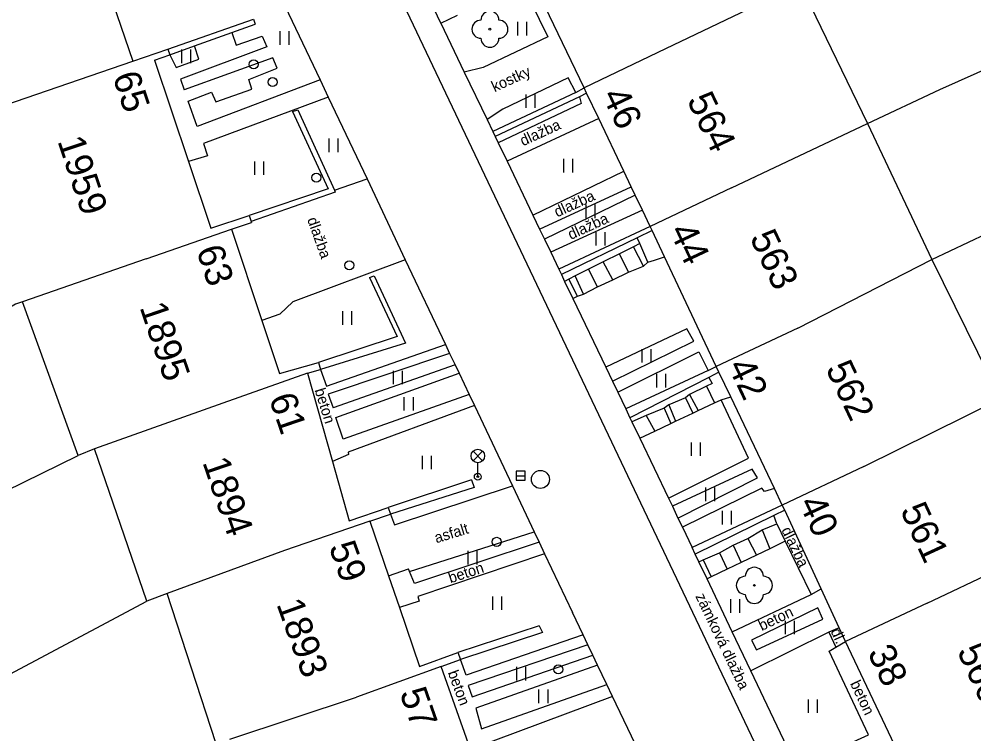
# Model space of a CAD drawing. Extents: x -493753 to -49290, y -1127285 to -112654.
# Drawn here: x -493226.3 to -493173.4, y -1127082.4 to -1127042.8 of the extents above; entities that cross this region are included whole.
import ezdxf

# ---------------------------------------------------------------- set-up
doc = ezdxf.new("R2010")
doc.units = 0
for name, color, linetype in [('Vrstva 10', 7, 'Continuous'), ('Vrstva 11', 7, 'Continuous'), ('Vrstva 22', 7, 'Continuous'), ('Vrstva 27', 7, 'Continuous'), ('Vrstva 28', 7, 'Continuous'), ('Vrstva 33', 7, 'Continuous'), ('Vrstva 36', 7, 'Continuous'), ('Vrstva 40', 7, 'Continuous'), ('Vrstva 43', 7, 'Continuous'), ('Vrstva 44', 7, 'Continuous'), ('Vrstva 5', 7, 'Continuous'), ('Vrstva 7', 7, 'Continuous')]:
    doc.layers.add(name, color=color, linetype=linetype)

msp = doc.modelspace()

# ---------------------------------------------------------------- linework, layer by layer
at = {"layer": 'Vrstva 10'}
for p, q in [((-493205.89, -1127040.18), (-493179.72, -1127095.23)), ((-493188.12, -1127062.66), (-493187.94, -1127063)), ((-493187.94, -1127063), (-493188.26, -1127063.14)), ((-493197.52, -1127071.79), (-493204.43, -1127074.07)), ((-493205.86, -1127073.65), (-493204.76, -1127073.27)), ((-493182.08, -1127075.43), (-493185.76, -1127077.21)), ((-493181.81, -1127076.05), (-493182.08, -1127075.43)), ((-493185.49, -1127077.76), (-493181.81, -1127076.05)), ((-493185.76, -1127077.21), (-493185.49, -1127077.76))]:
    msp.add_line(p, q, dxfattribs=at)
for points in [[(-493260.05, -1127044.84), (-493224.71, -1127032.96), (-493223.22, -1127032.61), (-493221.74, -1127032.78), (-493219.88, -1127033.49), (-493218.04, -1127034.37), (-493216.09, -1127035.82), (-493214.61, -1127037.23), (-493213.32, -1127038.83), (-493211.79, -1127041.66), (-493209.65, -1127046.18), (-493209.2, -1127047.13), (-493207.05, -1127051.66)], [(-493198.46, -1127040.88), (-493197.04, -1127043.79), (-493200.63, -1127045.49), (-493201.67, -1127045.75)], [(-493202.96, -1127043.04), (-493202.05, -1127042.6)], [(-493218.09, -1127044.47), (-493213.34, -1127042.82), (-493213.26, -1127043.09)], [(-493214.55, -1127043.55), (-493213.26, -1127043.09)], [(-493202.96, -1127043.04), (-493201.67, -1127045.75)], [(-493216.62, -1127044.3), (-493214.55, -1127043.55)], [(-493214.55, -1127043.55), (-493214.31, -1127044.26), (-493212.87, -1127043.75), (-493212.61, -1127044.34)], [(-493217.98, -1127044.79), (-493217.62, -1127045.5), (-493216.37, -1127045.03), (-493216.62, -1127044.3)], [(-493217.98, -1127044.79), (-493216.62, -1127044.3)], [(-493212.61, -1127044.34), (-493217.38, -1127046.13), (-493217.18, -1127046.72)], [(-493209.65, -1127046.18), (-493216.46, -1127048.76), (-493216.96, -1127047.35), (-493215.68, -1127046.85), (-493215.44, -1127047.4), (-493213.43, -1127046.69), (-493213.61, -1127046.15), (-493212.03, -1127045.52), (-493212.28, -1127044.95), (-493217.18, -1127046.72)], [(-493195.49, -1127046.87), (-493195.91, -1127046.07), (-493199.53, -1127047.8), (-493200.41, -1127048.38)], [(-493195.49, -1127046.87), (-493200.09, -1127049.03)], [(-493195.49, -1127046.87), (-493195.03, -1127046.62)], [(-493194.89, -1127046.92), (-493195.29, -1127047.11)], [(-493209.2, -1127047.13), (-493216.12, -1127049.7), (-493215.9, -1127050.38), (-493216.95, -1127050.69)], [(-493195.29, -1127047.11), (-493199.96, -1127049.31)], [(-493195.29, -1127047.11), (-493195.2, -1127047.49), (-493199.79, -1127049.67)], [(-493211.18, -1127047.93), (-493209.21, -1127052.22), (-493213.59, -1127053.69)], [(-493210.89, -1127047.83), (-493208.86, -1127052.29), (-493208.82, -1127052.39), (-493213.48, -1127054.03)], [(-493211.18, -1127047.93), (-493210.89, -1127047.83)], [(-493200.41, -1127048.38), (-493200.09, -1127049.03)], [(-493194.22, -1127048.31), (-493199.3, -1127050.68)], [(-493200.09, -1127049.03), (-493199.96, -1127049.31)], [(-493199.96, -1127049.31), (-493199.79, -1127049.67)], [(-493199.3, -1127050.68), (-493197.87, -1127053.68)], [(-493208.86, -1127052.29), (-493207.05, -1127051.66)], [(-493207.05, -1127051.66), (-493204.94, -1127056.14), (-493202.71, -1127060.84)], [(-493197.87, -1127053.68), (-493192.83, -1127051.23)], [(-493197.5, -1127054.45), (-493192.42, -1127052.1)], [(-493192.2, -1127052.56), (-493197.23, -1127055.01)], [(-493191.8, -1127053.4), (-493196.88, -1127055.73)], [(-493191.37, -1127054.3), (-493196.43, -1127056.67)], [(-493197.5, -1127054.45), (-493197.23, -1127055.01)], [(-493191.26, -1127054.53), (-493192.09, -1127054.93)], [(-493192.09, -1127054.93), (-493196.29, -1127056.96)], [(-493192.3, -1127055.42), (-493193.07, -1127055.81)], [(-493191.95, -1127055.25), (-493192.3, -1127055.42)], [(-493191.95, -1127055.25), (-493192.09, -1127054.93)], [(-493196.88, -1127055.73), (-493196.43, -1127056.67)], [(-493193.07, -1127055.81), (-493193.97, -1127056.26)], [(-493204.94, -1127056.14), (-493211.16, -1127058.48), (-493211.88, -1127059.15), (-493212.88, -1127059.51)], [(-493193.97, -1127056.26), (-493194.78, -1127056.67)], [(-493192.57, -1127056.83), (-493191.74, -1127056.49)], [(-493191.74, -1127056.49), (-493191.5, -1127056.27)], [(-493191.5, -1127056.27), (-493191.14, -1127056.16)], [(-493191.14, -1127056.16), (-493190.58, -1127055.98)], [(-493196.43, -1127056.67), (-493196.29, -1127056.96)], [(-493196.29, -1127056.96), (-493196.11, -1127057.34)], [(-493194.78, -1127056.67), (-493195.53, -1127057.04)], [(-493193.44, -1127057.25), (-493192.57, -1127056.83)], [(-493206.91, -1127057.13), (-493205.38, -1127060.4), (-493209.75, -1127061.83)], [(-493206.91, -1127057.13), (-493206.66, -1127057.03), (-493204.93, -1127060.76), (-493209.64, -1127062.22)], [(-493195.88, -1127057.22), (-493196.11, -1127057.34)], [(-493195.53, -1127057.04), (-493195.88, -1127057.22)], [(-493194.29, -1127057.65), (-493193.44, -1127057.25)], [(-493195.4, -1127058.16), (-493195.07, -1127058.04)], [(-493195.07, -1127058.04), (-493194.29, -1127057.65)], [(-493195.66, -1127058.28), (-493195.4, -1127058.16)], [(-493195.66, -1127058.28), (-493193.83, -1127062.09)], [(-493193.46, -1127062.86), (-493188.96, -1127060.66), (-493189.34, -1127059.97), (-493193.83, -1127062.09)], [(-493209.64, -1127062.22), (-493209.31, -1127063.14), (-493202.71, -1127060.84)], [(-493202.71, -1127060.84), (-493202.48, -1127061.33)], [(-493193.17, -1127063.48), (-493188.67, -1127061.24), (-493188.16, -1127062.27)], [(-493202.48, -1127061.33), (-493209.21, -1127063.58), (-493208.94, -1127064.35)], [(-493202.48, -1127061.33), (-493202.18, -1127061.96)], [(-493202.18, -1127061.96), (-493208.94, -1127064.35)], [(-493202.18, -1127061.96), (-493201.96, -1127062.42)], [(-493188.16, -1127062.27), (-493192.72, -1127064.41)], [(-493188.16, -1127062.27), (-493187.71, -1127062.06)], [(-493201.39, -1127063.61), (-493208.38, -1127066.08), (-493208.78, -1127064.88), (-493201.96, -1127062.42)], [(-493201.96, -1127062.42), (-493201.39, -1127063.61)], [(-493188.12, -1127062.66), (-493192.49, -1127064.9)], [(-493187.56, -1127062.37), (-493188.12, -1127062.66)], [(-493193.46, -1127062.86), (-493193.17, -1127063.48)], [(-493188.26, -1127063.14), (-493189.19, -1127063.6)], [(-493201.39, -1127063.61), (-493201.11, -1127064.22)], [(-493193.17, -1127063.48), (-493192.72, -1127064.41)], [(-493190.36, -1127069.35), (-493185.92, -1127067.14), (-493187.44, -1127063.9), (-493186.91, -1127063.74)], [(-493189.41, -1127063.8), (-493190.34, -1127064.18)], [(-493189.19, -1127063.6), (-493189.41, -1127063.8)], [(-493201.11, -1127064.22), (-493208.11, -1127066.81), (-493208.09, -1127066.93), (-493208.97, -1127067.32)], [(-493201.11, -1127064.22), (-493199, -1127068.66), (-493197.8, -1127071.21), (-493197.52, -1127071.79), (-493197.22, -1127072.44), (-493195.68, -1127075.68)], [(-493192.72, -1127064.41), (-493192.49, -1127064.9)], [(-493190.6, -1127064.36), (-493191.59, -1127064.77)], [(-493190.34, -1127064.18), (-493190.6, -1127064.36)], [(-493188.71, -1127064.5), (-493187.8, -1127064.07)], [(-493187.8, -1127064.07), (-493187.44, -1127063.9)], [(-493192.49, -1127064.9), (-493192.38, -1127065.13)], [(-493191.59, -1127064.77), (-493192.38, -1127065.13)], [(-493189.96, -1127065.09), (-493189, -1127064.64)], [(-493189, -1127064.64), (-493188.71, -1127064.5)], [(-493191.12, -1127065.64), (-493190.23, -1127065.22)], [(-493190.23, -1127065.22), (-493189.96, -1127065.09)], [(-493191.95, -1127066.03), (-493191.12, -1127065.64)], [(-493191.95, -1127066.03), (-493190.36, -1127069.35)], [(-493189.83, -1127070.45), (-493185.43, -1127068.23), (-493185.72, -1127067.75), (-493190.14, -1127069.8)], [(-493201.27, -1127068.33), (-493205.88, -1127069.86)], [(-493201.27, -1127068.33), (-493201.12, -1127068.76), (-493205.75, -1127070.24)], [(-493205.75, -1127070.24), (-493205.53, -1127070.83), (-493199, -1127068.66)], [(-493184.49, -1127068.81), (-493185.04, -1127068.99), (-493185.19, -1127068.79), (-493189.58, -1127070.96)], [(-493190.14, -1127069.8), (-493189.83, -1127070.45)], [(-493184.05, -1127069.74), (-493189.04, -1127072.09)], [(-493183.92, -1127070.02), (-493184.52, -1127070.31), (-493188.87, -1127072.46)], [(-493185.17, -1127071.11), (-493184.35, -1127070.77)], [(-493184.35, -1127070.77), (-493184.52, -1127070.31)], [(-493204.7, -1127073.41), (-493197.8, -1127071.21)], [(-493189.58, -1127070.96), (-493189.04, -1127072.09)], [(-493185.97, -1127071.59), (-493185.17, -1127071.11)], [(-493186.78, -1127071.96), (-493185.97, -1127071.59)], [(-493183.89, -1127071.74), (-493184.75, -1127072.15)], [(-493183.89, -1127071.74), (-493182.46, -1127074.69), (-493181.9, -1127074.37)], [(-493188.87, -1127072.46), (-493189.04, -1127072.09)], [(-493187.53, -1127072.38), (-493186.78, -1127071.96)], [(-493184.75, -1127072.15), (-493185.49, -1127072.5)], [(-493197.22, -1127072.44), (-493204.24, -1127074.8), (-493204.17, -1127075.05), (-493205.26, -1127075.41)], [(-493188.67, -1127072.87), (-493188.87, -1127072.46)], [(-493188.67, -1127072.87), (-493188.44, -1127072.77)], [(-493188.44, -1127072.77), (-493187.53, -1127072.38)], [(-493185.49, -1127072.5), (-493186.33, -1127072.91)], [(-493204.43, -1127074.07), (-493204.7, -1127073.41), (-493204.76, -1127073.27)], [(-493187.1, -1127073.28), (-493188, -1127073.71)], [(-493186.33, -1127072.91), (-493187.1, -1127073.28)], [(-493188, -1127073.71), (-493188.22, -1127073.82)], [(-493186.83, -1127076.75), (-493188.22, -1127073.82)], [(-493186.83, -1127076.75), (-493182.46, -1127074.69)], [(-493195.09, -1127076.92), (-493195.68, -1127075.68)], [(-493197.52, -1127076.42), (-493202.02, -1127077.9)], [(-493197.52, -1127076.42), (-493197.34, -1127076.8)], [(-493197.34, -1127076.8), (-493201.88, -1127078.28)], [(-493195.09, -1127076.92), (-493201.56, -1127079.15), (-493201.88, -1127078.28)], [(-493194.82, -1127077.47), (-493195.09, -1127076.92)], [(-493181.47, -1127076.78), (-493185.8, -1127078.91)], [(-493181.47, -1127076.78), (-493181.08, -1127077.61)], [(-493194.82, -1127077.47), (-493201.45, -1127079.73), (-493201.23, -1127080.36), (-493194.55, -1127078.04)], [(-493194.55, -1127078.04), (-493194.82, -1127077.47)], [(-493183.25, -1127084.28), (-493179.28, -1127082.47), (-493181.45, -1127077.82), (-493181.08, -1127077.61), (-493180.55, -1127077.29)], [(-493194.28, -1127078.61), (-493194.55, -1127078.04)], [(-493194.28, -1127078.61), (-493201.03, -1127080.99), (-493200.72, -1127082.12), (-493193.77, -1127079.67)], [(-493193.77, -1127079.67), (-493194.28, -1127078.61)], [(-493183.25, -1127084.28), (-493185.8, -1127078.91)], [(-493193.45, -1127080.34), (-493193.77, -1127079.67)], [(-493193.45, -1127080.34), (-493201.33, -1127083.28)], [(-493184.049, -1127099.968), (-493188.07, -1127091.57), (-493191.55, -1127084.31), (-493193.45, -1127080.34)]]:
    msp.add_lwpolyline(points, dxfattribs=at)
at = {"layer": 'Vrstva 11'}
for p, q in [((-493202.96, -1127043.04), (-493203.53, -1127041.87)), ((-493188.22, -1127073.82), (-493188.67, -1127072.87)), ((-493185.8, -1127078.91), (-493186.83, -1127076.75))]:
    msp.add_line(p, q, dxfattribs=at)
for points in [[(-493183.06, -1127040.88), (-493190.52, -1127044.45)], [(-493183.06, -1127040.88), (-493179.33, -1127048.6)], [(-493201.67, -1127045.75), (-493200.41, -1127048.38)], [(-493231.93, -1127049.23), (-493224.75, -1127046.76)], [(-493179.33, -1127048.6), (-493175.32, -1127046.71)], [(-493186.86, -1127052.15), (-493179.33, -1127048.6)], [(-493179.33, -1127048.6), (-493175.77, -1127056.12)], [(-493199.79, -1127049.67), (-493199.3, -1127050.68)], [(-493197.87, -1127053.68), (-493197.5, -1127054.45)], [(-493175.77, -1127056.12), (-493171.71, -1127054.21)], [(-493197.23, -1127055.01), (-493196.88, -1127055.73)], [(-493191.74, -1127056.49), (-493192.3, -1127055.42)], [(-493191.5, -1127056.27), (-493191.95, -1127055.25)], [(-493192.57, -1127056.83), (-493193.07, -1127055.81)], [(-493219.29, -1127056.09), (-493226.14, -1127058.48)], [(-493193.44, -1127057.25), (-493193.97, -1127056.26)], [(-493183.19, -1127059.93), (-493175.77, -1127056.12)], [(-493175.77, -1127056.12), (-493171.97, -1127063.84)], [(-493194.29, -1127057.65), (-493194.78, -1127056.67)], [(-493196.11, -1127057.34), (-493195.66, -1127058.28)], [(-493195.4, -1127058.16), (-493195.88, -1127057.22)], [(-493195.07, -1127058.04), (-493195.53, -1127057.04)], [(-493226.14, -1127058.48), (-493226.52, -1127058.61), (-493245.45, -1127069.96)], [(-493223.06, -1127066.98), (-493226.14, -1127058.48)], [(-493193.83, -1127062.09), (-493193.46, -1127062.86)], [(-493188.26, -1127063.14), (-493187.8, -1127064.07)], [(-493189.41, -1127063.8), (-493189, -1127064.64)], [(-493189.19, -1127063.6), (-493188.71, -1127064.5)], [(-493179.54, -1127067.59), (-493171.97, -1127063.84)], [(-493215.05, -1127064.09), (-493222.16, -1127066.61)], [(-493190.6, -1127064.36), (-493190.23, -1127065.22)], [(-493190.34, -1127064.18), (-493189.96, -1127065.09)], [(-493191.59, -1127064.77), (-493191.12, -1127065.64)], [(-493192.38, -1127065.13), (-493191.95, -1127066.03)], [(-493233.13, -1127071.92), (-493223.06, -1127066.98)], [(-493222.16, -1127066.61), (-493223.06, -1127066.98)], [(-493219.25, -1127075.05), (-493222.16, -1127066.61)], [(-493190.36, -1127069.35), (-493190.14, -1127069.8)], [(-493189.83, -1127070.45), (-493189.58, -1127070.96)], [(-493184.35, -1127070.77), (-493183.89, -1127071.74)], [(-493185.17, -1127071.11), (-493184.75, -1127072.15)], [(-493185.97, -1127071.59), (-493185.49, -1127072.5)], [(-493176.03, -1127075.16), (-493168.24, -1127071.48)], [(-493211.63, -1127072.25), (-493218.12, -1127074.63)], [(-493186.78, -1127071.96), (-493186.33, -1127072.91)], [(-493188.44, -1127072.77), (-493188, -1127073.71)], [(-493187.53, -1127072.38), (-493187.1, -1127073.28)], [(-493218.12, -1127074.63), (-493219.25, -1127075.05)], [(-493215.44, -1127082.91), (-493218.12, -1127074.63)], [(-493228.8, -1127080.14), (-493219.25, -1127075.05)], [(-493180.9, -1127076.54), (-493181.47, -1127076.78)], [(-493214.65, -1127082.7), (-493207.64, -1127080.38)]]:
    msp.add_lwpolyline(points, dxfattribs=at)
at = {"layer": 'Vrstva 22'}
for centre in [(-493200.25, -1127043.37), (-493185.6, -1127074.18)]:
    msp.add_circle(centre, 0.05, dxfattribs=at)
for centre, start, end in [((-493200.25, -1127042.87), 360, 180), ((-493200.75, -1127043.37), 90, 270), ((-493199.75, -1127043.37), 270, 90), ((-493200.25, -1127043.87), 180, 0), ((-493185.6, -1127073.68), 360, 180), ((-493186.1, -1127074.18), 90, 270), ((-493185.1, -1127074.18), 270, 90), ((-493185.6, -1127074.68), 180, 0)]:
    msp.add_arc(centre, 0.5, start, end, dxfattribs=at)
at = {"layer": 'Vrstva 27'}
msp.add_line((-493198.79, -1127068.11), (-493198.29, -1127068.11), dxfattribs=at)
msp.add_lwpolyline([(-493198.79, -1127068.36), (-493198.29, -1127068.36), (-493198.29, -1127067.86), (-493198.79, -1127067.86)], close=True, dxfattribs=at)
msp.add_circle((-493197.45, -1127068.31), 0.5, dxfattribs=at)
at = {"layer": 'Vrstva 28'}
for centre in [(-493213.34, -1127045.32), (-493212.29, -1127046.3), (-493209.86, -1127051.59), (-493208.04, -1127056.45), (-493199.87, -1127071.77), (-493196.46, -1127078.84)]:
    msp.add_circle(centre, 0.25, dxfattribs=at)
at = {"layer": 'Vrstva 33'}
for p, q in [((-493201.185, -1127066.745), (-493200.655, -1127067.275)), ((-493201.185, -1127067.275), (-493200.655, -1127066.745)), ((-493200.92, -1127068.16), (-493200.92, -1127067.385))]:
    msp.add_line(p, q, dxfattribs=at)
for centre, radius in [((-493200.92, -1127067.01), 0.375), ((-493200.92, -1127068.16), 0.19), ((-493200.92, -1127068.16), 0.05)]:
    msp.add_circle(centre, radius, dxfattribs=at)
at = {"layer": 'Vrstva 36'}
for p, q in [((-493198.7, -1127043.71), (-493198.7, -1127042.96)), ((-493198.2, -1127043.71), (-493198.2, -1127042.96)), ((-493211.87, -1127044.23), (-493211.87, -1127043.48)), ((-493211.37, -1127044.23), (-493211.37, -1127043.48)), ((-493217.32, -1127045.25), (-493217.32, -1127044.5)), ((-493216.82, -1127045.25), (-493216.82, -1127044.5)), ((-493198.24, -1127047.73), (-493198.24, -1127046.98)), ((-493197.74, -1127047.73), (-493197.74, -1127046.98)), ((-493209.16, -1127050.18), (-493209.16, -1127049.43)), ((-493208.66, -1127050.18), (-493208.66, -1127049.43)), ((-493196.16, -1127051.3), (-493196.16, -1127050.55)), ((-493195.66, -1127051.3), (-493195.66, -1127050.55)), ((-493213.27, -1127051.44), (-493213.27, -1127050.69)), ((-493212.77, -1127051.44), (-493212.77, -1127050.69)), ((-493194.91, -1127053.84), (-493194.91, -1127053.09)), ((-493194.41, -1127053.84), (-493194.41, -1127053.09)), ((-493194.37, -1127055.36), (-493194.37, -1127054.61)), ((-493193.87, -1127055.36), (-493193.87, -1127054.61)), ((-493208.39, -1127059.74), (-493208.39, -1127058.99)), ((-493207.89, -1127059.74), (-493207.89, -1127058.99)), ((-493191.81, -1127061.84), (-493191.81, -1127061.09)), ((-493191.31, -1127061.84), (-493191.31, -1127061.09)), ((-493205.59, -1127063.04), (-493205.59, -1127062.29)), ((-493205.09, -1127063.04), (-493205.09, -1127062.29)), ((-493191, -1127063.22), (-493191, -1127062.47)), ((-493190.5, -1127063.22), (-493190.5, -1127062.47)), ((-493204.99, -1127064.5), (-493204.99, -1127063.75)), ((-493204.49, -1127064.5), (-493204.49, -1127063.75)), ((-493189.09, -1127067.01), (-493189.09, -1127066.26)), ((-493188.59, -1127067.01), (-493188.59, -1127066.26)), ((-493203.99, -1127067.75), (-493203.99, -1127067)), ((-493203.49, -1127067.75), (-493203.49, -1127067)), ((-493188.29, -1127069.51), (-493188.29, -1127068.76)), ((-493187.79, -1127069.51), (-493187.79, -1127068.76)), ((-493187.36, -1127070.81), (-493187.36, -1127070.06)), ((-493186.86, -1127070.81), (-493186.86, -1127070.06)), ((-493201.45, -1127073.02), (-493201.45, -1127072.27)), ((-493200.95, -1127073.02), (-493200.95, -1127072.27)), ((-493200.08, -1127075.54), (-493200.08, -1127074.79)), ((-493199.58, -1127075.54), (-493199.58, -1127074.79)), ((-493186.91, -1127075.7), (-493186.91, -1127074.95)), ((-493186.41, -1127075.7), (-493186.41, -1127074.95)), ((-493183.87, -1127076.89), (-493183.87, -1127076.14)), ((-493183.37, -1127076.89), (-493183.37, -1127076.14)), ((-493198.75, -1127079.45), (-493198.75, -1127078.7)), ((-493198.25, -1127079.45), (-493198.25, -1127078.7)), ((-493197.53, -1127080.7), (-493197.53, -1127079.95)), ((-493197.03, -1127080.7), (-493197.03, -1127079.95)), ((-493182.6, -1127081.25), (-493182.6, -1127080.5)), ((-493182.1, -1127081.25), (-493182.1, -1127080.5))]:
    msp.add_line(p, q, dxfattribs=at)
at = {"layer": 'Vrstva 5'}
for p, q in [((-493220.03, -1127045.14), (-493218.09, -1127044.47)), ((-493218.82, -1127045.08), (-493217.98, -1127044.79)), ((-493218.09, -1127044.47), (-493217.98, -1127044.79)), ((-493190.52, -1127044.45), (-493195.03, -1127046.62)), ((-493224.75, -1127046.76), (-493220.03, -1127045.14)), ((-493186.86, -1127052.15), (-493191.37, -1127054.3)), ((-493215.71, -1127054.4), (-493213.59, -1127053.69)), ((-493214.57, -1127054.45), (-493213.46, -1127054.08)), ((-493219.29, -1127056.09), (-493214.57, -1127054.45)), ((-493183.19, -1127059.93), (-493187.71, -1127062.06)), ((-493211.91, -1127062.44), (-493209.75, -1127061.83)), ((-493210.35, -1127062.42), (-493209.64, -1127062.22)), ((-493209.75, -1127061.83), (-493209.64, -1127062.22)), ((-493210.35, -1127062.42), (-493215.05, -1127064.09)), ((-493179.54, -1127067.59), (-493184.05, -1127069.74)), ((-493208.04, -1127070.6), (-493205.88, -1127069.86)), ((-493206.9, -1127070.63), (-493205.75, -1127070.24)), ((-493205.88, -1127069.86), (-493205.75, -1127070.24)), ((-493206.9, -1127070.63), (-493211.63, -1127072.25)), ((-493176.03, -1127075.16), (-493180.55, -1127077.29)), ((-493204.15, -1127078.67), (-493202.02, -1127077.9)), ((-493202.02, -1127077.9), (-493201.88, -1127078.28)), ((-493202.94, -1127078.68), (-493207.64, -1127080.38))]:
    msp.add_line(p, q, dxfattribs=at)
for points in [[(-493195.03, -1127046.62), (-493197.91, -1127040.62), (-493198.75, -1127038.88), (-493187.22, -1127033.3)], [(-493223.12, -1127036.13), (-493221.14, -1127041.9), (-493220.03, -1127045.14)], [(-493218.82, -1127045.08), (-493216.95, -1127050.69), (-493215.71, -1127054.4)], [(-493191.37, -1127054.3), (-493191.8, -1127053.4), (-493192.2, -1127052.56), (-493192.42, -1127052.1), (-493192.83, -1127051.23), (-493194.22, -1127048.31), (-493194.89, -1127046.92), (-493195.03, -1127046.62)], [(-493213.59, -1127053.69), (-493213.48, -1127054.03), (-493213.46, -1127054.08)], [(-493187.71, -1127062.06), (-493190.58, -1127055.98), (-493191.26, -1127054.53), (-493191.37, -1127054.3)], [(-493214.57, -1127054.45), (-493212.88, -1127059.51), (-493211.91, -1127062.44)], [(-493184.05, -1127069.74), (-493184.49, -1127068.81), (-493186.91, -1127063.74), (-493187.56, -1127062.37), (-493187.71, -1127062.06)], [(-493210.35, -1127062.42), (-493208.97, -1127067.32), (-493208.04, -1127070.6)], [(-493180.55, -1127077.29), (-493180.9, -1127076.54), (-493181.9, -1127074.37), (-493183.92, -1127070.02), (-493184.05, -1127069.74)], [(-493206.9, -1127070.63), (-493205.86, -1127073.65), (-493205.26, -1127075.41), (-493204.15, -1127078.67)], [(-493176.85, -1127085.1), (-493176.89, -1127085.02), (-493177.32, -1127084.1), (-493180.55, -1127077.29)], [(-493202.94, -1127078.68), (-493201.88, -1127078.28)], [(-493200.14, -1127086.68), (-493201.33, -1127083.28), (-493202.94, -1127078.68)]]:
    msp.add_lwpolyline(points, dxfattribs=at)
at = {"layer": 'Vrstva 7'}
msp.add_line((-493175.32, -1127046.71), (-493166.2, -1127042.6), dxfattribs=at)

# ---------------------------------------------------------------- texts
at = {"layer": 'Vrstva 40'}
for s, rotation, p in [('kostky', 24.6669, (-493199.992, -1127046.864)), ('dlažba', 24.6972, (-493198.415, -1127049.859)), ('dlažba', 24.6972, (-493196.525, -1127053.799)), ('dlažba', 289.6182, (-493210.38, -1127053.906)), ('dlažba', 24.6972, (-493195.765, -1127055.049)), ('beton', 287.4261, (-493209.968, -1127063.358)), ('asfalt', 17.0617, (-493203.215, -1127071.851)), ('dlažba', 295.8256, (-493184.12, -1127071.112)), ('beton', 18.0778, (-493202.435, -1127074.07)), ('zámková dlažba', 295.4258, (-493188.878, -1127074.783)), ('beton', 25.3594, (-493185.194, -1127076.715)), ('dl.', 294.2727, (-493181.391, -1127076.711)), ('beton', 290.4658, (-493202.592, -1127079.013)), ('beton', 295.0887, (-493180.31, -1127079.612))]:
    msp.add_text(s, height=0.6, rotation=rotation, dxfattribs=at).set_placement(p)
at = {"layer": 'Vrstva 43'}
for s, rotation, p in [('564', 295.4783, (-493189.358, -1127047.295)), ('1959', 288.4316, (-493224.216, -1127049.562)), ('563', 295.2532, (-493185.877, -1127054.912)), ('1895', 288.6818, (-493219.666, -1127058.765)), ('562', 295.4821, (-493181.673, -1127062.168)), ('1894', 288.8924, (-493216.185, -1127067.357)), ('561', 294.8736, (-493177.541, -1127070.017)), ('1893', 289.8492, (-493212.087, -1127075.216)), ('560', 294.8736, (-493174.395, -1127077.817))]:
    msp.add_text(s, height=1.5, rotation=rotation, dxfattribs=at).set_placement(p)
at = {"layer": 'Vrstva 44'}
for s, rotation, p in [('65', 288.4316, (-493221.166, -1127045.984)), ('46', 295.4783, (-493194.066, -1127047.032)), ('44', 295.2532, (-493190.332, -1127054.534)), ('63', 288.6557, (-493216.53, -1127055.608)), ('42', 295.4821, (-493187.101, -1127062.021)), ('61', 288.8924, (-493212.508, -1127063.81)), ('40', 294.8736, (-493183.17, -1127069.612)), ('59', 289.8492, (-493209.188, -1127072.041)), ('38', 295.3052, (-493179.353, -1127077.899)), ('57', 289.2962, (-493205.264, -1127080.131))]:
    msp.add_text(s, height=1.5, rotation=rotation, dxfattribs=at).set_placement(p)

doc.saveas('drawing.dxf')
